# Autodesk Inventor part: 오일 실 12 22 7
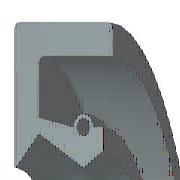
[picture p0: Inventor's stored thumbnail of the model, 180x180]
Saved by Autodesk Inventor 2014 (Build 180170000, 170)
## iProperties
IsCustomPart: 1
Created: 2012-02
Part Number: 오일 실 12 22 7
Material: 고무
Description: 오일-실
Document SubType Name: Modeling
Standard: KS B 2804
Designer: mduedu
Standards Organization: KS
Language: ko-KR
Size Designation: D - 12 22 7
Categories: <MemberInstance><Categories><Category DisplayName="샤프트 부품" InternalName="7f7aeb1f-a693-4053-b835-cee3144e0d98" Mnemonic="SHFT"><Category DisplayName="실링" Intern
Density: 0.93 g/cm^3
Mass: 1.25383 g
Surface Area: 18.4996 cm^2
Volume: 1.3482 cm^3
Appearance: 고무 - 검은색 - 버전 1.1
Author: mduedu
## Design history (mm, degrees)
revolve "본체" stored, may be unused: angle "d17" = 90 deg
revolve "스프링1" stored, may be unused: angle "d18" = 90 deg
body "Solid1"
sketch "스케치1"
  geometry: L1 (0, 11)-(7, 11); L2 (7, 9.25)-(1.75, 9.25); L3 (1.75, 7.75)-(4.9, 6); L4 (4.9, 6)-(0, 6); L5 (0, 0)-(9.586, 0) reference; L6 (4.9, 6)-(6.3, 6.875); L7 (0, 18)-(0, -3) reference; L8 (-1.941, 0)-(11.507, 0) reference; L9 (4.2, 8.1)-(1.75, 8.59); L10 (1.75, 8.59)-(1.75, 9.25); L11 (0, 11)-(0, 6.088); L12 (4.9, 6)-(0, 6); L13 (1.75, 7.75)-(0.152, 6.028); L14 (7, 11)-(7, 9.25); L15 (5.6, 8.1)-(6.3, 8.1); L16 (6.3, 8.1)-(6.3, 6.875); C1 r 0.455 at (4.9, 8.1); A1 r 0.7 centre (4.9, 8.1) between (5.6, 8.1) and (4.2, 8.1); A2 r 0.088 centre (0.088, 6.088) between (0, 6.088) and (0.152, 6.028); 1 further point
  constraints: 28 end point, 5 horizontal alignment, 5 point on line, 4 point on circle, 4 vertical alignment, 3 centre point, 3 tangent, 2 collinear, 2 horizontal, 2 perpendicular, 1 coincident, 1 parallel
  dimensions: "d0" = 22 diameter of L1 L5 (= SD2); "d1" = 1.75 distance of L1.end L2.start (= SD); "d2" = 0.91 diameter of C1 (= SPDI); "d3" = 1.4 diameter of A1 (= SPDA); "d4" = 12 diameter of L3.end L5 (= NND); "d5" = 15.5 diameter of L3.start L5 (= TKDM); "d7" = 17.18 diameter of L9.end L5 (= TKDM + 0.24 x SWDT); "d8" = 1.75 distance between parallel lines of L11 L10 (= SD); "d9" = 4.9 distance from line of L11 C1.centre (= SPDST); "d10" = 16.2 diameter of C1.centre L5 (= HLDM); "d11" = 0.0875 radius of A2 (= 0.25 x LAB); "d12" = 6.3 distance between parallel lines of L11 L16 (= SDI); "d13" = 13.75 diameter of L6.end L5 (= ABDM); "d14" = 7 distance from line of L11 L1.end (= SWDT)
fillet "모깎기1" dims "d6" = 0.3 (= RR)
other parameters: "SD2" = 22 [user parameter; used in 1 equation term], "SWDT" = 7 [user parameter; used in 2 equation terms], "RR" = 0.3 [user parameter; used in 1 equation term], "SD" = 1.75 [user parameter; used in 2 equation terms], "NND" = 12 [user parameter; used in 1 equation term], "SPDA" = 1.4 [user parameter; used in 1 equation term], "SPDI" = 0.91 [user parameter; used in 1 equation term], "TKDM" = 15.5 [user parameter; used in 2 equation terms], "HLDM" = 16.2 [user parameter; used in 1 equation term], "ABDM" = 13.75 [user parameter; used in 1 equation term], "SDI" = 6.3 [user parameter; used in 1 equation term], "SPDST" = 4.9 [user parameter; used in 1 equation term], "LAB" = 0.35 [user parameter; used in 1 equation term], "d15" = 0, "d16" = 0, "d19" = 0
